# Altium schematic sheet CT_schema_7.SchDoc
size 368 x 243 mm
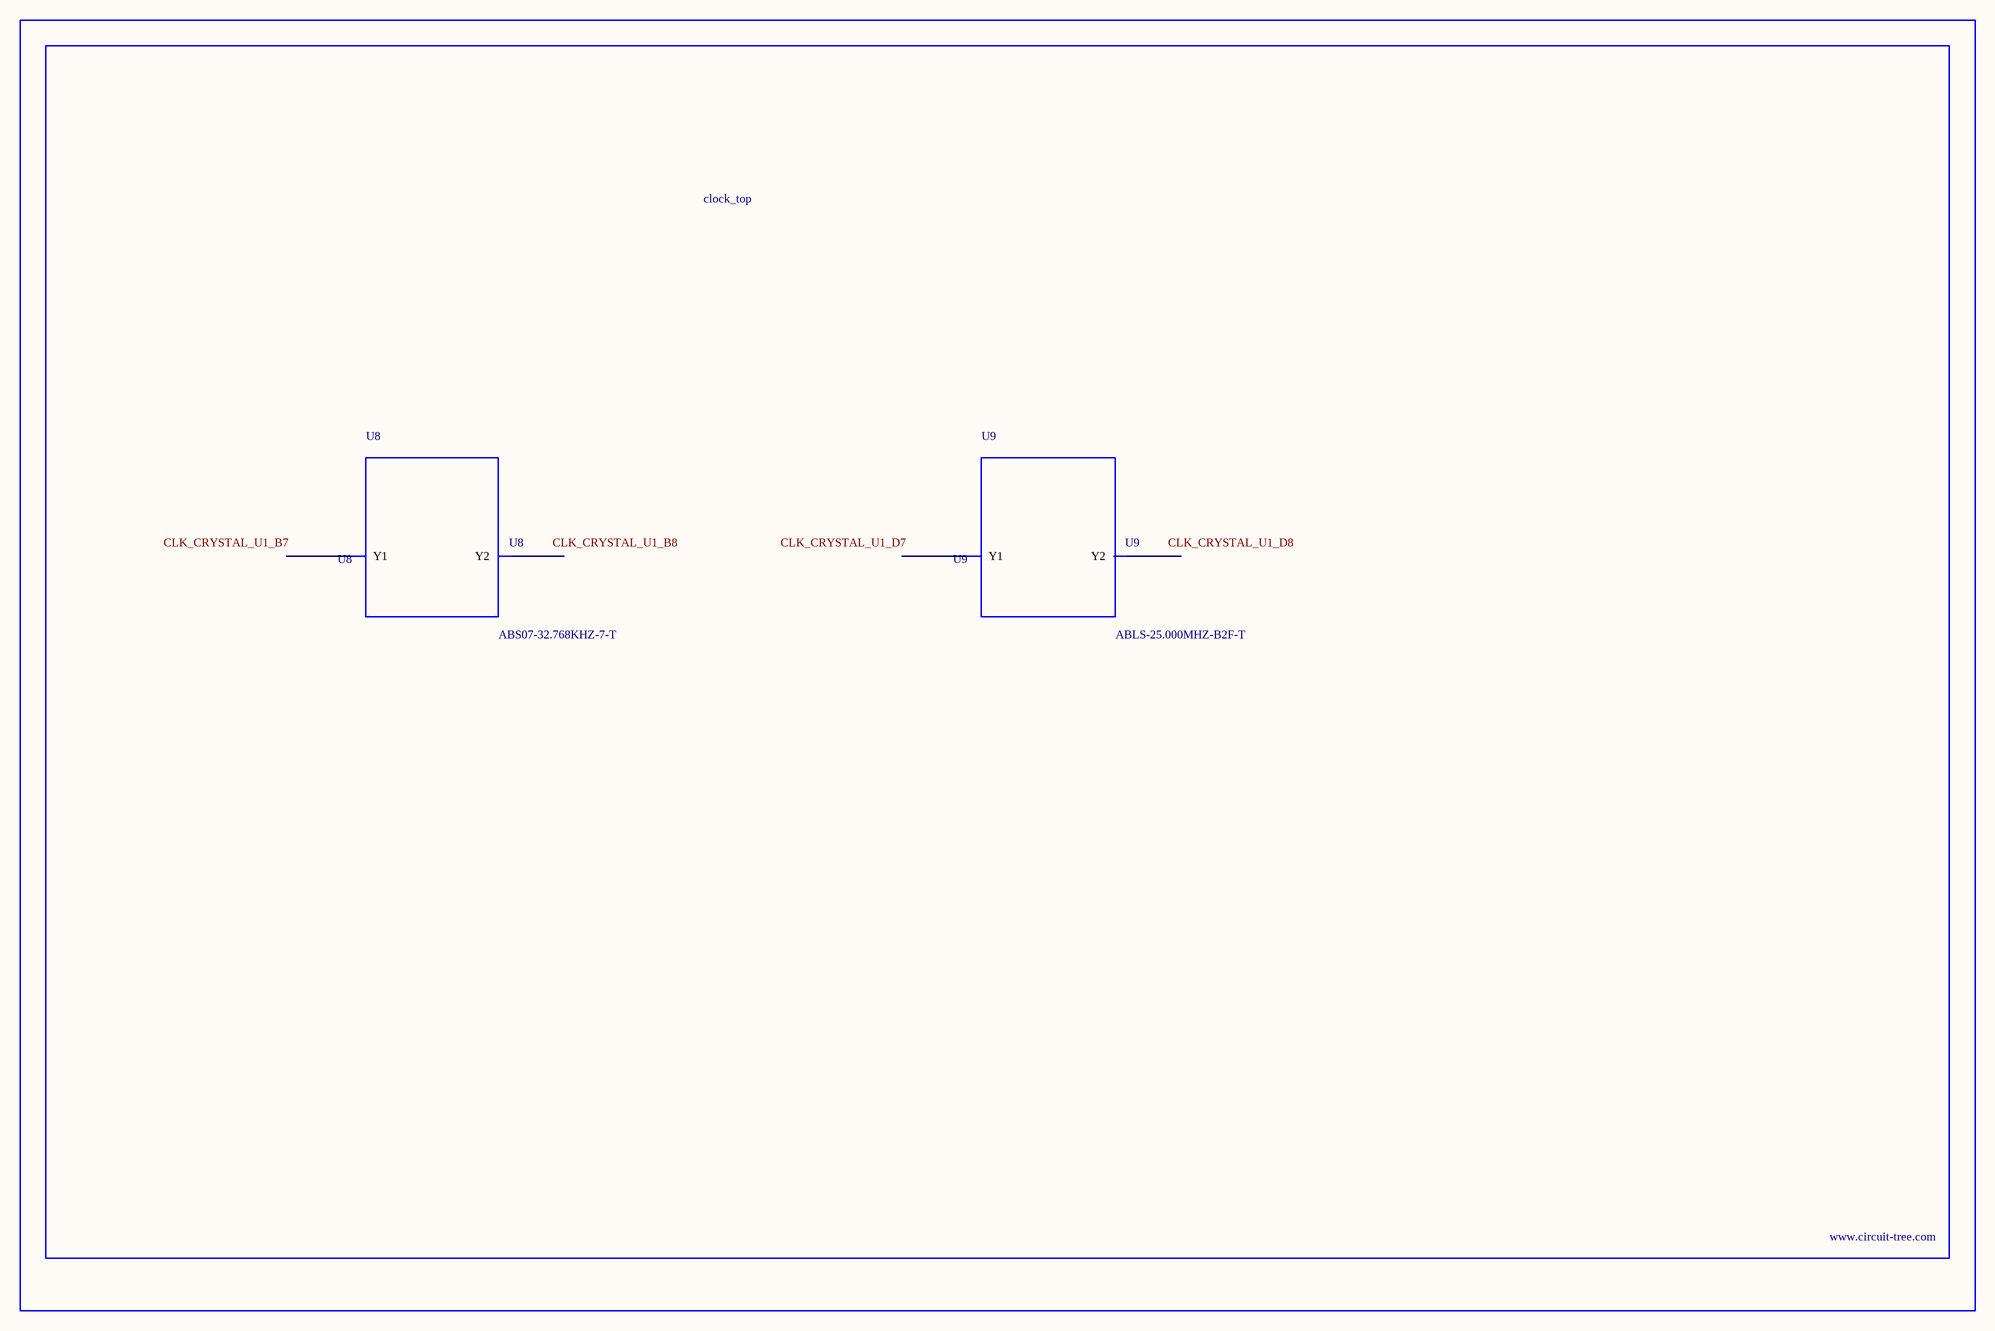
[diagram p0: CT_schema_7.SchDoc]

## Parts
BORDER6  (no value)
U8  ABS07-32.768KHZ-7-T  [ABS07-32.768KHZ-7-T]
U9  ABLS-25.000MHZ-B2F-T  [ABLS-25.000MHZ-B2F-T]

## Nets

Not connected (* = marked no-connect by the designer): U8 1(Y1) 2(Y2); U9 1(Y1) 2(Y2)

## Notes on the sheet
- Labels drawn without touching a wire or pin: CLK_CRYSTAL_U1_B7, CLK_CRYSTAL_U1_B8, CLK_CRYSTAL_U1_D7, CLK_CRYSTAL_U1_D8

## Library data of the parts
BORDER6 = BORDER_PAGE6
